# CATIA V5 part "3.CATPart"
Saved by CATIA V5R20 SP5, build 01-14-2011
Part number: 3
Bounding box of the stored display mesh (mm): x -106.5 to -93.5, y -24 to 26, z 3.5 to 16.5
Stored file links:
  F:\CAD\很靠后、\3.CATPart
  F:\CAD\很靠后、\1.CATPart
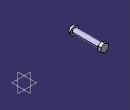
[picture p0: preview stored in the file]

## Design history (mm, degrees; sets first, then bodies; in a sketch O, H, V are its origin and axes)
Body1 (main body)
Body2
  Sketch1 on zx-plane, origin (0, 0, 0), H (-1, 0, 0), V (0, 0, 1)
    circle A1 centre (100, 10) radius 4
    radius A1 = 4
  Pad1: profile Sketch1, direction (0, 1, 0), length 21, mirrored extent
  Sketch2 on start face of Pad1, origin (0, -21, 0), H (1, 0, 0), V (0, 0, 1)
    circle A1 centre (-100, 10) radius 6.5
    radius A1 = 6.5
  Pad2: profile Sketch2, direction (0, -1, 0), length 3
  Sketch3 on end face of Pad1, origin (0, 21, 0), H (-1, 0, 0), V (0, 0, 1)
    point P1 (100, 10)
    point P2 (105.6292, 6.75)
    point P3 (105.6292, 13.25)
    point P4 (100, 16.5)
    point P5 (94.3708, 13.25)
    point P6 (94.3708, 6.75)
    point P7 (100, 3.5)
    point P8 (105.6292, 10)
    line L1 (105.6292, 6.75) -> (105.6292, 13.25)
    line L2 (105.6292, 13.25) -> (100, 16.5)
    line L3 (100, 16.5) -> (94.3708, 13.25)
    line L4 (94.3708, 13.25) -> (94.3708, 6.75)
    line L5 (94.3708, 6.75) -> (100, 3.5)
    line L6 (100, 3.5) -> (105.6292, 6.75)
    construction line L7 (100, 10) -> (105.6292, 10)
    construction circle A1 centre (100, 10) radius 6.5
    construction arc A2 centre (94.3708, 6.75) radius 6.5 from (94.3708, 13.25) to (100, 3.5) cw
    construction arc A3 centre (105.6292, 13.25) radius 6.5 from (100, 16.5) to (105.6292, 6.75) ccw
    radius A1 = 6.5
    coincidence: A1 P2, A1 P3, A1 P4, A1 P5, A1 P6, A1 P7, A2 P1, A3 P1
    midpoint: P8 L1
    parallelism: L1 L4
  Pad3: profile Sketch3, direction (0, 1, 0), length 5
